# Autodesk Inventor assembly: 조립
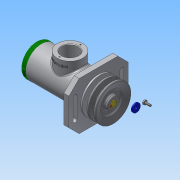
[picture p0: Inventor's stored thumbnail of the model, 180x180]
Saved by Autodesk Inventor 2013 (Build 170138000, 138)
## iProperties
Created: 2017-10
Part Number: 조립
Document SubType Name: Assembly
Designer: Administrator
Author: Administrator
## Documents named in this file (17)
- C:\Users\Administrator\Desktop\471008V1020\조립.iam
- C:\Users\Administrator\Desktop\471008V1020\본체.ipt
- C:\Users\Administrator\Desktop\471008V1020\축.ipt
- C:\Users\Administrator\Desktop\471008V1020\부시1.ipt
- C:\Users\Administrator\Desktop\471008V1020\베어링 15 x 35 x 11.ipt
- C:\Users\Administrator\Desktop\471008V1020\멈춤링 35x1.6.ipt
- C:\Users\Administrator\Desktop\471008V1020\부시2.ipt
- C:\Users\Administrator\Desktop\471008V1020\와셔 10x21.ipt
- C:\Users\Administrator\Desktop\471008V1020\너트 M10.ipt
- C:\Users\Administrator\Desktop\471008V1020\사이드 커버.ipt
- 사이드 커버.ipt
- C:\Users\Administrator\Desktop\471008V1020\멈춤링 15 x 1.ipt
- C:\Users\Administrator\Desktop\471008V1020\오일 실 15 25 7.ipt
- C:\Users\Administrator\Desktop\471008V1020\V-벨트풀리.ipt
- C:\Users\Administrator\Desktop\471008V1020\볼트 M4 x 10.ipt
- C:\Users\Administrator\Desktop\471008V1020\와셔 4x16.ipt
- C:\Users\Administrator\Desktop\471008V1020\키 4 x 4 x 18.ipt
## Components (2 placed, 2 different names)
1. V-벨트풀리:1
2. ISO 4017 M4 x 10:1
